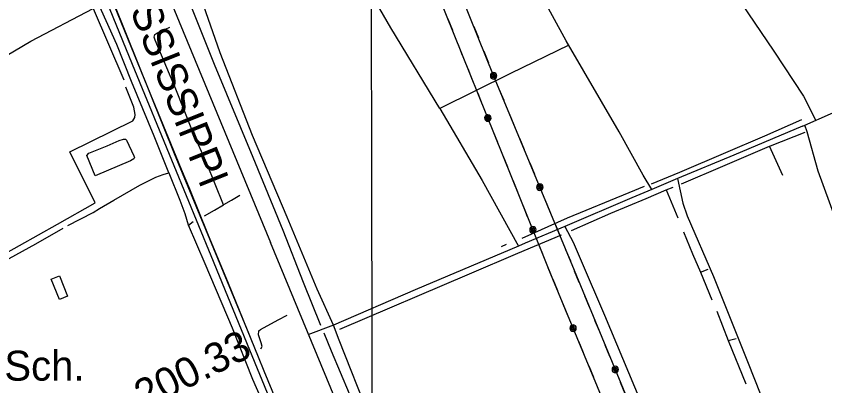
# Model space of a CAD drawing. Extents: x 3329332 to 3367211, y 631066 to 656469.
# Drawn here: x 3353510 to 3355751, y 640639 to 641662 of the extents above; entities that cross this region are included whole.
import ezdxf

# ---------------------------------------------------------------- set-up
doc = ezdxf.new("R2010")
doc.units = 0
for name, color, linetype in [('V-BLDG-IDEN', 7, 'Continuous'), ('V-BLDG-OTLN', 7, 'Continuous'), ('V-DTCH-CNTR', 7, 'Continuous'), ('V-GRID-MAJR', 7, 'Continuous'), ('V-RAIL-IDEN', 7, 'Continuous'), ('V-RAIL-TRAK', 7, 'Continuous'), ('V-RIVR-RANG-IDEN', 7, 'Continuous'), ('V-ROAD-CNTR', 7, 'Continuous'), ('V-TOPO-SHOR', 7, 'Continuous'), ('V-UTIL-LINE', 7, 'Continuous')]:
    doc.layers.add(name, color=color, linetype=linetype)

msp = doc.modelspace()

# ---------------------------------------------------------------- linework, layer by layer
at = {"layer": 'V-BLDG-OTLN'}
msp.add_lwpolyline([(3353629.8, 640942.9), (3353652.2, 640886.9), (3353629.7, 640877.9), (3353607.3, 640933.9)], close=True, dxfattribs=at)
at = {"layer": 'V-DTCH-CNTR'}
for p, q in [((3353723, 641683.6), (3353808.8, 641486.2)), ((3355691.9, 641440.6), (3355725.9, 641373.9))]:
    msp.add_line(p, q, dxfattribs=at)
for points in [[(3353158.8, 641360.1), (3353264.4, 641424.2), (3353327.6, 641462.6), (3353550.9, 641592.8), (3353723, 641683.6), (3353661, 641850.8), (3353557.7, 642104.1), (3353448.7, 642329.2), (3353362.3, 642539.1), (3353332.6, 642608.6), (3353325.8, 642617.6), (3353309.3, 642621.1), (3353270.9, 642617.9), (3353243.4, 642614.7), (3353220.7, 642607.3), (3353153.8, 642561.1), (3353067.7, 642504.7), (3353043.6, 642495.2), (3353017.5, 642494), (3352994.8, 642489.4), (3352968.7, 642476.5), (3352901.1, 642426.2), (3352753.6, 642615.6)], [(3355013.7, 642444.9), (3355128.7, 642273.3), (3355360.4, 641933.8), (3355609.7, 641565.8), (3355691.9, 641440.6)], [(3355271.2, 641182.5), (3355247.8, 641222.3), (3355180.8, 641342.5), (3355034.6, 641594.2), (3354963.8, 641723.5), (3354918.6, 641800.8), (3354807, 641992.9), (3354748.1, 642101.9), (3354694.8, 642200.3), (3354668.5, 642243.9)], [(3355689.4, 641357.8), (3355695.4, 641360.5), (3355838.1, 641423.5), (3356049.4, 641516.1), (3356281.1, 641610.7), (3356475.6, 641693.5), (3356718.2, 641798), (3356944.4, 641890.8), (3357131.4, 641968), (3357366.9, 642069.8), (3357547.9, 642139.4), (3357557, 641943.7), (3357555, 641730), (3357514.7, 641729.4), (3357487.6, 641808.2), (3357303.9, 641739), (3357129.4, 641675.6), (3356959.4, 641612.1), (3356761.6, 641542.7), (3356562.1, 641473), (3356475.6, 641693.5)], [(3354684.2, 641407.2), (3354548.5, 641630), (3354456.6, 641789.2), (3354393.2, 641900.5), (3354372.9, 641936.1), (3354323.2, 642041.9)], [(3354389, 640806.4), (3354344.3, 640906.3), (3354261.4, 641106), (3354164.8, 641332.1), (3354075.6, 641561.2), (3354035.3, 641674.2), (3354002.3, 641773.2), (3353977.4, 641838.6)], [(3355041.4, 641582.5), (3354880, 641503.5), (3354684.2, 641407.2), (3354801.1, 641207.5), (3354902.3, 641025.7)], [(3352690.7, 641087.8), (3352742.1, 640990.8), (3352812.1, 640842.4), (3352883.5, 640685.3), (3352889.4, 640680.8), (3352897.4, 640682.2), (3352926.8, 640697.4), (3353108.3, 640796.5), (3353198.9, 640847.7), (3353360.4, 640939.1), (3353624.2, 641086.6), (3353729.3, 641145.2), (3353658.5, 641287), (3353833.4, 641373), (3353839.3, 641381.7), (3353840.1, 641389.8), (3353835.8, 641410.3), (3353813.5, 641465.4)], [(3355689.4, 641357.8), (3355498.5, 641277.8), (3355343, 641212.6), (3355271.2, 641182.5), (3355216.5, 641159.6), (3355030.3, 641080.2), (3354920.6, 641033.5), (3354902.3, 641025.7), (3354615.9, 640904.4), (3354389, 640806.4), (3354317.9, 640779.8)], [(3355682.6, 640101.4), (3355788.5, 640123.1), (3355952.6, 640158.2), (3356046.6, 640176.9), (3356030.5, 640260.9), (3356016.2, 640321.8), (3355984.8, 640411.6), (3355961.7, 640490.8), (3355927.5, 640613.3), (3355887.9, 640740.7), (3355861, 640832.6), (3355823.9, 640959.6), (3355781.6, 641099.8), (3355732.8, 641232.9), (3355701.7, 641342.6), (3355695.4, 641360.5)], [(3355343, 641212.6), (3355357.2, 641144.8), (3355370, 641109.3), (3355442.8, 640941.8), (3355538.9, 640701), (3355605.6, 640533.6), (3355614.7, 640515.8), (3355623.1, 640509.6), (3355631.5, 640506.4), (3355648.5, 640506.3), (3355677.8, 640516.9)], [(3355030.3, 641080.2), (3355053.9, 641036.2), (3355075.9, 640985.3), (3355140.3, 640834), (3355257, 640556.9), (3355381.9, 640248.2), (3355422.2, 640140.4), (3355423.5, 640137), (3355425.7, 640130.1), (3355429.4, 640103.1), (3355433.9, 640080), (3355439.9, 640066.1), (3355451.4, 640057.6), (3355459.1, 640055.2), (3355477.6, 640058.2), (3355682.6, 640101.4)], [(3355226, 640088.3), (3355077.8, 640047.4), (3354919.6, 639993.6), (3354802, 639954), (3354780.6, 639949.5), (3354760.8, 639954.2), (3354738.8, 639971.9), (3354718.5, 640006.3), (3354670.4, 640118.7), (3354585.6, 640316.7), (3354488.9, 640552.9), (3354404.9, 640765.4), (3354389, 640806.4)]]:
    msp.add_lwpolyline(points, dxfattribs=at)
at = {"layer": 'V-GRID-MAJR'}
msp.add_spline([(3354505.6, 636487.8), (3354493.2, 642546.1), (3354480.9, 648607.4), (3354468.6, 654668.8), (3354468.6, 654671.8)], degree=3, dxfattribs=at)
at = {"layer": 'V-RAIL-TRAK'}
for points in [[(3354667, 639534.7), (3354616.9, 639633.5), (3354597, 639671), (3354586.7, 639694.9), (3354530.2, 639831.1), (3354456.1, 640012.2), (3354364.3, 640234.4), (3354268.1, 640467.8), (3354158, 640737.9), (3354050, 640999.1), (3353948, 641248.2), (3353832.7, 641528.8), (3353725.5, 641791.4), (3353598.5, 642100.4), (3353474.5, 642402.7), (3353325.4, 642764.8), (3353219.7, 643021.5), (3353113.2, 643278.9), (3353098.8, 643314.2), (3352989.9, 643581.1), (3352910.9, 643771)], [(3353781.6, 641691.8), (3353874.1, 641465.8), (3353967.3, 641238.4), (3353990.1, 641184.5), (3354040.7, 641060.3), (3354097.3, 640922.6), (3354181, 640719.1), (3354196.4, 640680.2), (3354278.6, 640481.9), (3354352.8, 640301.6), (3354376.3, 640244), (3354462.2, 640033), (3354562, 639789.1), (3354667, 639534.7), (3354769.8, 639280.6), (3354779.3, 639257.1), (3354889.4, 638990.7), (3354993, 638740.1), (3355122.9, 638422.1), (3355220.5, 638183.4), (3355289.6, 638016.6)]]:
    msp.add_lwpolyline(points, dxfattribs=at)
at = {"layer": 'V-ROAD-CNTR'}
for points in [[(3350055.8, 651140.1), (3350440.1, 650230.7), (3350657.6, 649703.2), (3351013.6, 648831.3), (3351205.9, 648365.5), (3351409.9, 647864.4), (3351543.9, 647537.5), (3351727.1, 647084.5), (3351868.7, 646739.5), (3352018.3, 646380), (3352260.8, 645783.7), (3352611.2, 644939.6), (3352855.7, 644340.9), (3353071.6, 643816), (3353365, 643105.6), (3353609, 642507.1), (3353763.8, 642127.3), (3353961.4, 641646.4), (3354215.3, 641035.3)], [(3349932.6, 651050.5), (3350283.7, 650214.4), (3350591.5, 649465.9), (3350897.3, 648721.3), (3351095, 648236), (3351427.6, 647425.4), (3351649.7, 646885.6), (3351805.6, 646510.6), (3351997.4, 646041.9), (3352187.7, 645566), (3352363.9, 645133.8), (3352574.7, 644627.6), (3352794.9, 644090.5), (3353015.5, 643552.8), (3353189.8, 643129.1), (3353379.8, 642671), (3353592.3, 642161.2), (3353746.1, 641783.8), (3353947.8, 641281.9), (3354155.1, 640782.9)], [(3355130.2, 638809.5), (3354961, 639219.6), (3354586.9, 640137.7), (3354215.3, 641035.3)]]:
    msp.add_lwpolyline(points, dxfattribs=at)
at = {"layer": 'V-TOPO-SHOR'}
for p, q in [((3355634.3, 641221.6), (3355598, 641302.3)), ((3355311.1, 641181.1), (3355343.8, 641104.4)), ((3354855.4, 641024.8), (3354869.2, 641030.8)), ((3355406.1, 640953.5), (3355438, 640876.8)), ((3355482.8, 640763.8), (3355532.2, 640644.6))]:
    msp.add_line(p, q, dxfattribs=at)
for points in [[(3354354.8, 640806.1), (3354306.2, 640925.3), (3354250, 641068.5), (3354166.5, 641271.3), (3354060.1, 641528.3), (3353994.8, 641690.1), (3353950, 641803.9)], [(3353987.8, 641083.7), (3353978.7, 641115.4), (3353964.3, 641151.8), (3353933.9, 641227.6), (3353933.5, 641228.7), (3353892.9, 641330.6), (3353829.9, 641481.5), (3353788.9, 641583.7), (3353730.3, 641716.1), (3353746.6, 641723.7)], [(3354084.5, 641140.4), (3354038.2, 641254.1), (3354000.2, 641339.3), (3353952.4, 641460.1), (3353895.4, 641595.6), (3353892.3, 641604.1), (3353893.9, 641611.8), (3353900.1, 641615.6), (3353935.8, 641632.3)], [(3355270.5, 641198.1), (3355349.2, 641230.3), (3355476.9, 641285.1), (3355584.7, 641330.9), (3355687.1, 641376)], [(3353728.8, 641220.3), (3353706, 641276.9), (3353711.4, 641283), (3353762.5, 641303.5), (3353795.8, 641318), (3353807.4, 641321.8), (3353812.8, 641321.7), (3353815.9, 641318.6), (3353836.5, 641276), (3353838, 641271.4), (3353836.4, 641267.5), (3353827.1, 641262.2), (3353728.8, 641220.3)], [(3355354.3, 641198.3), (3355475.1, 641250.1), (3355598, 641302.3), (3355600.5, 641303.4), (3355696.8, 641340.8)], [(3353653, 641082.4), (3353723.2, 641118.3), (3353741.2, 641129.9), (3353780.4, 641153), (3353852.8, 641194.4), (3353896.9, 641216.7), (3353917.5, 641224.1), (3353933.5, 641228.7)], [(3354912, 641048), (3355038.1, 641103.6), (3355208.6, 641174.1), (3355251.4, 641191.4)], [(3355048.6, 641068.5), (3355157.9, 641117.3), (3355255.7, 641157.8), (3355311.1, 641181.1), (3355330.7, 641189.3)], [(3354032, 641109.6), (3354059.9, 641124.9), (3354084.5, 641140.4), (3354085.4, 641140.9), (3354106.4, 641153.1), (3354129.6, 641166.9)], [(3352881.8, 640652.3), (3352967.3, 640698.4), (3353066.5, 640753.4), (3353145.1, 640802.3), (3353178.2, 640818.5), (3353201.6, 640829.4), (3353223.6, 640840.9), (3353249.1, 640856.5), (3353309.1, 640891.1), (3353336, 640906.7), (3353415.9, 640950.8), (3353564.1, 641031.5), (3353639.9, 641074.9)], [(3353749.9, 640380.4), (3353838.2, 640419.2), (3353922.6, 640455.7), (3354027.1, 640502.1), (3354117, 640543.2), (3354192.8, 640571.2), (3354199, 640575.8), (3354196.8, 640587.4), (3354166.3, 640656.3), (3354109.4, 640798), (3354033.4, 640976.1), (3353987.8, 641083.7), (3354001, 641093.6)], [(3354407.1, 640795.3), (3354766.5, 640949.1), (3354900.2, 641006.2), (3355021, 641057.2)], [(3355359, 641065), (3355384.8, 641003.8), (3355406.1, 640953.5), (3355427.7, 640961.8)], [(3354187.8, 640741.1), (3354191.7, 640748), (3354189.4, 640757.3), (3354181.8, 640779.8), (3354182.7, 640790.6), (3354187.3, 640794.4), (3354236.2, 640821.1), (3354261, 640834.8)], [(3355451.7, 640845.1), (3355482.8, 640763.8), (3355505.2, 640769.8)], [(3354723.2, 639909.7), (3354678.4, 640024.2), (3354605.6, 640205.3), (3354540.2, 640355.6), (3354458.9, 640557.6), (3354383.7, 640734.9), (3354363.9, 640784.4)]]:
    msp.add_lwpolyline(points, dxfattribs=at)
at = {"layer": 'V-UTIL-LINE'}
for points in [[(3355057, 640957.9), (3354832.9, 641498.1), (3354614.4, 642039.4), (3354397.9, 642569), (3354160.1, 643137.5), (3353936.7, 643682.3), (3353706.1, 644246.6), (3353477.2, 644804.1), (3353249.1, 645361.4), (3353019.3, 645913.3), (3352822.6, 646394.7), (3352634.2, 646842.1), (3352469.8, 647270.3), (3352329.5, 647842.2)], [(3354997, 640934.2), (3354562.2, 642013.6), (3354336, 642554.4), (3354106.7, 643114.4), (3353883.4, 643654.7), (3353653.6, 644219.7), (3353419.4, 644779.3), (3353196.6, 645329.8), (3352962.2, 645897), (3352767.7, 646365.7), (3352563.9, 646828.2), (3352422, 647304), (3352297.4, 647805.2)], [(3354719.8, 641622.5), (3354707.1, 641654.1)], [(3354778.2, 641633.7), (3354790.9, 641602.2)], [(3354747.4, 641553.9), (3354734.7, 641585.4)], [(3354805.9, 641565.1), (3354818.6, 641533.6)], [(3354775.1, 641485.2), (3354762.4, 641516.8)], [(3354833.2, 641497.4), (3354834.7, 641499.8), (3354832.4, 641499.8), (3354831, 641497.4), (3354832.4, 641494.8), (3354835.6, 641496), (3354837.5, 641500.3), (3354834.4, 641503.2), (3354829.5, 641502.6), (3354827.6, 641498.4), (3354828.4, 641494), (3354832.6, 641491.8), (3354837.8, 641493.6), (3354841.5, 641500.9), (3354839.5, 641503.8), (3354836.6, 641505.7), (3354833.2, 641506.4), (3354829.7, 641505.7), (3354826.8, 641503.8), (3354824.9, 641500.9), (3354824.2, 641497.4), (3354824.9, 641494), (3354826.8, 641491.1), (3354829.7, 641489.1), (3354833.2, 641488.4), (3354836.6, 641489.1), (3354839.6, 641491.1), (3354841.5, 641494), (3354842.2, 641497.4), (3354841.5, 641500.9)], [(3354848.1, 641461.4), (3354861.2, 641430)], [(3354802.7, 641416.6), (3354790, 641448.1)], [(3354817.3, 641380.4), (3354815.7, 641378), (3354818, 641378.1), (3354819.5, 641380.4), (3354818.1, 641383), (3354814.9, 641381.9), (3354812.9, 641377.6), (3354816, 641374.7), (3354820.9, 641375.2), (3354822.9, 641379.3), (3354822.1, 641383.7), (3354817.9, 641386), (3354812.7, 641384.3), (3354808.9, 641377.1), (3354810.9, 641374.1), (3354813.8, 641372.1), (3354817.2, 641371.4), (3354820.6, 641372.1), (3354823.6, 641374), (3354825.6, 641376.9), (3354826.3, 641380.3), (3354825.6, 641383.8), (3354823.7, 641386.7), (3354820.8, 641388.7), (3354817.4, 641389.4), (3354813.9, 641388.8), (3354811, 641386.8), (3354809, 641383.9), (3354808.3, 641380.5), (3354808.9, 641377.1)], [(3354876.5, 641393.1), (3354889.5, 641361.6)], [(3354844.6, 641312.7), (3354831.9, 641344.2)], [(3354904.8, 641324.7), (3354917.9, 641293.3)], [(3354872.2, 641244.1), (3354859.5, 641275.6)], [(3354933.2, 641256.3), (3354946.2, 641224.9)], [(3354899.9, 641175.4), (3354887.1, 641207)], [(3354961.2, 641188.9), (3354962.7, 641191.3), (3354960.4, 641191.2), (3354959, 641188.9), (3354960.4, 641186.3), (3354963.6, 641187.5), (3354965.5, 641191.8), (3354962.3, 641194.7), (3354957.5, 641194.1), (3354955.6, 641189.9), (3354956.3, 641185.5), (3354960.6, 641183.3), (3354965.8, 641185.1), (3354969.5, 641192.4), (3354967.5, 641195.3), (3354964.6, 641197.2), (3354961.2, 641197.9), (3354957.7, 641197.2), (3354954.8, 641195.3), (3354952.8, 641192.4), (3354952.2, 641188.9), (3354952.9, 641185.5), (3354954.8, 641182.6), (3354957.7, 641180.6), (3354961.2, 641179.9), (3354964.6, 641180.6), (3354967.5, 641182.6), (3354969.5, 641185.5), (3354970.2, 641188.9), (3354969.5, 641192.4)], [(3354976.1, 641152.9), (3354989.1, 641121.5)], [(3354927.5, 641106.8), (3354914.8, 641138.3)], [(3354942.1, 641070.6), (3354940.5, 641068.2), (3354942.8, 641068.3), (3354944.3, 641070.6), (3354942.9, 641073.2), (3354939.7, 641072.1), (3354937.7, 641067.8), (3354940.8, 641064.9), (3354945.7, 641065.4), (3354947.7, 641069.5), (3354946.9, 641073.9), (3354942.7, 641076.2), (3354937.5, 641074.5), (3354933.7, 641067.2), (3354935.6, 641064.3), (3354938.5, 641062.3), (3354942, 641061.6), (3354945.4, 641062.3), (3354948.4, 641064.2), (3354950.4, 641067.1), (3354951.1, 641070.5), (3354950.4, 641074), (3354948.5, 641076.9), (3354945.6, 641078.9), (3354942.2, 641079.6), (3354938.7, 641079), (3354935.8, 641077), (3354933.8, 641074.1), (3354933.1, 641070.7), (3354933.7, 641067.2)], [(3355004.5, 641084.5), (3355017.5, 641053.1)], [(3354969.3, 641002.9), (3354956.6, 641034.4)], [(3355032.8, 641016.2), (3355045.8, 640984.8)], [(3354997, 640934.2), (3354984.3, 640965.8)], [(3356375, 637770.1), (3355057, 640957.9)], [(3355070.6, 640925), (3355057.6, 640956.4)], [(3356319.9, 637747.2), (3354997, 640934.2)], [(3354997, 640934.2), (3355010, 640902.8)], [(3355098.9, 640856.6), (3355085.9, 640888.1)], [(3355025.4, 640865.9), (3355038.4, 640834.5)], [(3355053.4, 640798.5), (3355054.9, 640800.9), (3355052.6, 640800.8), (3355051.2, 640798.5), (3355052.6, 640795.9), (3355055.8, 640797.1), (3355057.7, 640801.3), (3355054.5, 640804.2), (3355049.7, 640803.6), (3355047.7, 640799.5), (3355048.5, 640795.1), (3355052.8, 640792.8), (3355058, 640794.7), (3355061.7, 640801.9), (3355059.7, 640804.8), (3355056.8, 640806.8), (3355053.3, 640807.5), (3355049.9, 640806.8), (3355047, 640804.8), (3355045, 640801.9), (3355044.4, 640798.5), (3355045, 640795), (3355047, 640792.1), (3355049.9, 640790.2), (3355053.4, 640789.5), (3355056.8, 640790.2), (3355059.7, 640792.1), (3355061.7, 640795), (3355062.4, 640798.5), (3355061.7, 640801.9)], [(3355127.1, 640788.3), (3355114.1, 640819.7)], [(3355068.3, 640762.5), (3355081.3, 640731.1)], [(3355155.4, 640719.9), (3355142.4, 640751.3)], [(3355096.7, 640694.1), (3355109.7, 640662.7)], [(3355170.3, 640683.9), (3355168.7, 640681.4), (3355171.1, 640681.5), (3355172.5, 640683.9), (3355171.1, 640686.4), (3355167.9, 640685.3), (3355166, 640681), (3355169.1, 640678.1), (3355173.9, 640678.7), (3355175.9, 640682.8), (3355175.1, 640687.2), (3355170.9, 640689.5), (3355165.7, 640687.7), (3355162, 640680.4), (3355163.9, 640677.5), (3355166.9, 640675.5), (3355170.3, 640674.9), (3355173.7, 640675.5), (3355176.7, 640677.5), (3355178.6, 640680.4), (3355179.3, 640683.8), (3355178.6, 640687.3), (3355176.7, 640690.2), (3355173.8, 640692.2), (3355170.3, 640692.9), (3355166.9, 640692.2), (3355163.9, 640690.2), (3355162, 640687.3), (3355161.3, 640683.9), (3355162, 640680.4)], [(3355198.2, 640616.4), (3355185.2, 640647.8)]]:
    msp.add_lwpolyline(points, dxfattribs=at)

# ---------------------------------------------------------------- texts
at = {"layer": 'V-BLDG-IDEN'}
msp.add_text('Sch.', height=83, dxfattribs=at).set_placement((3353477.3, 640653))
at = {"layer": 'V-RAIL-IDEN'}
msp.add_text('MISSISSIPPI', height=83, rotation=291.828, dxfattribs=at).set_placement((3353779, 641794))
at = {"layer": 'V-RIVR-RANG-IDEN'}
msp.add_text('R-200.33', height=83, rotation=26.6251, dxfattribs=at).set_placement((3353759.8, 640517.9))

doc.saveas('drawing.dxf')
